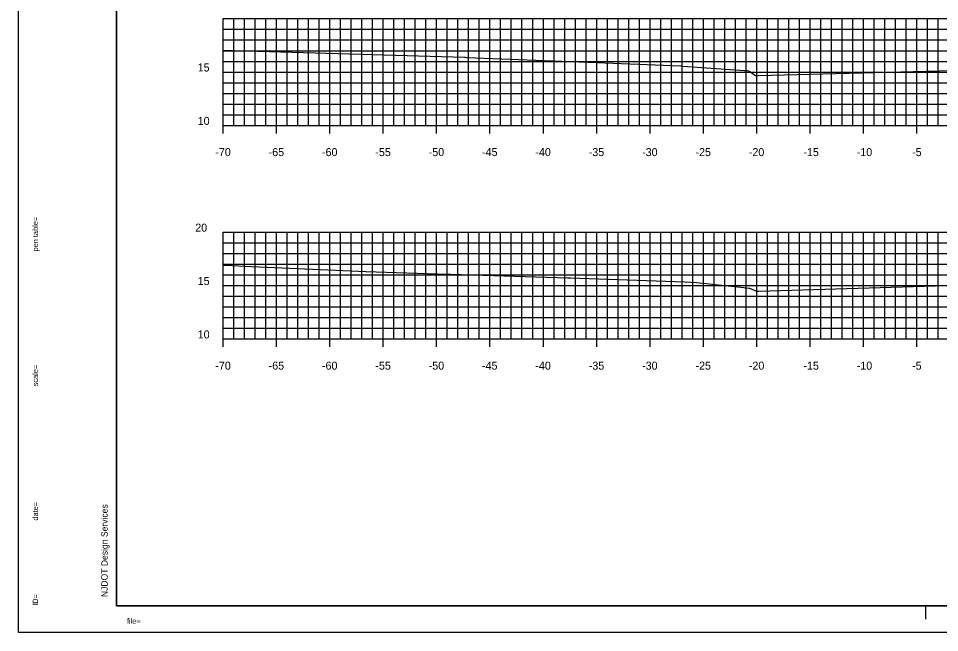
# Model space of a CAD drawing. Extents: x 40011 to 50684, y 49949 to 72236.
# Drawn here: x 40293.9 to 40380.3, y 71574.2 to 71631.7 of the extents above; entities that cross this region are included whole.
import ezdxf

# ---------------------------------------------------------------- set-up
doc = ezdxf.new("R2010")
doc.units = 0
for name, color, linetype in [('1', 7, 'Continuous'), ('41', 7, 'Continuous'), ('51', 7, 'Continuous'), ('52', 7, 'Continuous'), ('53', 7, 'Continuous'), ('54', 7, 'Continuous'), ('55', 7, 'Continuous'), ('57', 7, 'Continuous')]:
    doc.layers.add(name, color=color, linetype=linetype)

msp = doc.modelspace()

# ---------------------------------------------------------------- linework, layer by layer
at = {"layer": '1'}
for p, q in [((40303.141, 71681.691), (40303.141, 71576.691)), ((40303.141, 71576.691), (40468.141, 71576.691)), ((40378.974, 71575.441), (40378.974, 71576.691)), ((40468.641, 71574.191), (40293.946, 71574.191))]:
    msp.add_line(p, q, dxfattribs=at)
at = {"layer": '41'}
for points in [[(40293.946, 71684.191), (40468.641, 71684.191), (40468.641, 71574.191), (40293.946, 71574.191)], [(40303.141, 71681.691), (40468.141, 71681.691), (40468.141, 71576.691), (40303.141, 71576.691)]]:
    msp.add_lwpolyline(points, close=True, dxfattribs=at)
at = {"layer": '51'}
for p, q in [((40313.141, 71621.691), (40313.141, 71631.691)), ((40313.141, 71631.691), (40313.891, 71631.691)), ((40313.141, 71626.691), (40313.891, 71626.691)), ((40313.141, 71621.691), (40313.891, 71621.691)), ((40313.141, 71601.691), (40313.141, 71611.691)), ((40313.141, 71611.691), (40313.891, 71611.691)), ((40313.141, 71606.691), (40313.891, 71606.691)), ((40313.141, 71601.691), (40313.891, 71601.691))]:
    msp.add_line(p, q, dxfattribs=at)
at = {"layer": '52'}
for p, q in [((40313.141, 71621.691), (40453.141, 71621.691)), ((40313.141, 71620.941), (40313.141, 71621.691)), ((40318.141, 71620.941), (40318.141, 71621.691)), ((40323.141, 71620.941), (40323.141, 71621.691)), ((40328.141, 71620.941), (40328.141, 71621.691)), ((40333.141, 71620.941), (40333.141, 71621.691)), ((40338.141, 71620.941), (40338.141, 71621.691)), ((40343.141, 71620.941), (40343.141, 71621.691)), ((40348.141, 71620.941), (40348.141, 71621.691)), ((40353.141, 71620.941), (40353.141, 71621.691)), ((40358.141, 71620.941), (40358.141, 71621.691)), ((40363.141, 71620.941), (40363.141, 71621.691)), ((40368.141, 71620.941), (40368.141, 71621.691)), ((40373.141, 71620.941), (40373.141, 71621.691)), ((40378.141, 71620.941), (40378.141, 71621.691)), ((40313.141, 71601.691), (40453.141, 71601.691)), ((40313.141, 71600.941), (40313.141, 71601.691)), ((40318.141, 71600.941), (40318.141, 71601.691)), ((40323.141, 71600.941), (40323.141, 71601.691)), ((40328.141, 71600.941), (40328.141, 71601.691)), ((40333.141, 71600.941), (40333.141, 71601.691)), ((40338.141, 71600.941), (40338.141, 71601.691)), ((40343.141, 71600.941), (40343.141, 71601.691)), ((40348.141, 71600.941), (40348.141, 71601.691)), ((40353.141, 71600.941), (40353.141, 71601.691)), ((40358.141, 71600.941), (40358.141, 71601.691)), ((40363.141, 71600.941), (40363.141, 71601.691)), ((40368.141, 71600.941), (40368.141, 71601.691)), ((40373.141, 71600.941), (40373.141, 71601.691)), ((40378.141, 71600.941), (40378.141, 71601.691))]:
    msp.add_line(p, q, dxfattribs=at)
at = {"layer": '53'}
for p, q in [((40313.141, 71630.691), (40453.141, 71630.691)), ((40313.141, 71629.691), (40453.141, 71629.691)), ((40313.141, 71628.691), (40453.141, 71628.691)), ((40313.141, 71627.691), (40453.141, 71627.691)), ((40313.141, 71625.691), (40453.141, 71625.691)), ((40313.141, 71624.691), (40453.141, 71624.691)), ((40313.141, 71623.691), (40453.141, 71623.691)), ((40313.141, 71622.691), (40453.141, 71622.691)), ((40313.141, 71610.691), (40453.141, 71610.691)), ((40313.141, 71609.691), (40453.141, 71609.691)), ((40313.141, 71608.691), (40453.141, 71608.691)), ((40313.141, 71607.691), (40453.141, 71607.691)), ((40313.141, 71605.691), (40453.141, 71605.691)), ((40313.141, 71604.691), (40453.141, 71604.691)), ((40313.141, 71603.691), (40453.141, 71603.691)), ((40313.141, 71602.691), (40453.141, 71602.691))]:
    msp.add_line(p, q, dxfattribs=at)
at = {"layer": '54'}
for p, q in [((40314.141, 71621.691), (40314.141, 71631.691)), ((40315.141, 71621.691), (40315.141, 71631.691)), ((40316.141, 71621.691), (40316.141, 71631.691)), ((40317.141, 71621.691), (40317.141, 71631.691)), ((40319.141, 71621.691), (40319.141, 71631.691)), ((40320.141, 71621.691), (40320.141, 71631.691)), ((40321.141, 71621.691), (40321.141, 71631.691)), ((40322.141, 71621.691), (40322.141, 71631.691)), ((40324.141, 71621.691), (40324.141, 71631.691)), ((40325.141, 71621.691), (40325.141, 71631.691)), ((40326.141, 71621.691), (40326.141, 71631.691)), ((40327.141, 71621.691), (40327.141, 71631.691)), ((40329.141, 71621.691), (40329.141, 71631.691)), ((40330.141, 71621.691), (40330.141, 71631.691)), ((40331.141, 71621.691), (40331.141, 71631.691)), ((40332.141, 71621.691), (40332.141, 71631.691)), ((40334.141, 71621.691), (40334.141, 71631.691)), ((40335.141, 71621.691), (40335.141, 71631.691)), ((40336.141, 71621.691), (40336.141, 71631.691)), ((40337.141, 71621.691), (40337.141, 71631.691)), ((40339.141, 71621.691), (40339.141, 71631.691)), ((40340.141, 71621.691), (40340.141, 71631.691)), ((40341.141, 71621.691), (40341.141, 71631.691)), ((40342.141, 71621.691), (40342.141, 71631.691)), ((40344.141, 71621.691), (40344.141, 71631.691)), ((40345.141, 71621.691), (40345.141, 71631.691)), ((40346.141, 71621.691), (40346.141, 71631.691)), ((40347.141, 71621.691), (40347.141, 71631.691)), ((40349.141, 71621.691), (40349.141, 71631.691)), ((40350.141, 71621.691), (40350.141, 71631.691)), ((40351.141, 71621.691), (40351.141, 71631.691)), ((40352.141, 71621.691), (40352.141, 71631.691)), ((40354.141, 71621.691), (40354.141, 71631.691)), ((40355.141, 71621.691), (40355.141, 71631.691)), ((40356.141, 71621.691), (40356.141, 71631.691)), ((40357.141, 71621.691), (40357.141, 71631.691)), ((40359.141, 71621.691), (40359.141, 71631.691)), ((40360.141, 71621.691), (40360.141, 71631.691)), ((40361.141, 71621.691), (40361.141, 71631.691)), ((40362.141, 71621.691), (40362.141, 71631.691)), ((40364.141, 71621.691), (40364.141, 71631.691)), ((40365.141, 71621.691), (40365.141, 71631.691)), ((40366.141, 71621.691), (40366.141, 71631.691)), ((40367.141, 71621.691), (40367.141, 71631.691)), ((40369.141, 71621.691), (40369.141, 71631.691)), ((40370.141, 71621.691), (40370.141, 71631.691)), ((40371.141, 71621.691), (40371.141, 71631.691)), ((40372.141, 71621.691), (40372.141, 71631.691)), ((40374.141, 71621.691), (40374.141, 71631.691)), ((40375.141, 71621.691), (40375.141, 71631.691)), ((40376.141, 71621.691), (40376.141, 71631.691)), ((40377.141, 71621.691), (40377.141, 71631.691)), ((40379.141, 71621.691), (40379.141, 71631.691)), ((40380.141, 71621.691), (40380.141, 71631.691)), ((40314.141, 71601.691), (40314.141, 71611.691)), ((40315.141, 71601.691), (40315.141, 71611.691)), ((40316.141, 71601.691), (40316.141, 71611.691)), ((40317.141, 71601.691), (40317.141, 71611.691)), ((40319.141, 71601.691), (40319.141, 71611.691)), ((40320.141, 71601.691), (40320.141, 71611.691)), ((40321.141, 71601.691), (40321.141, 71611.691)), ((40322.141, 71601.691), (40322.141, 71611.691)), ((40324.141, 71601.691), (40324.141, 71611.691)), ((40325.141, 71601.691), (40325.141, 71611.691)), ((40326.141, 71601.691), (40326.141, 71611.691)), ((40327.141, 71601.691), (40327.141, 71611.691)), ((40329.141, 71601.691), (40329.141, 71611.691)), ((40330.141, 71601.691), (40330.141, 71611.691)), ((40331.141, 71601.691), (40331.141, 71611.691)), ((40332.141, 71601.691), (40332.141, 71611.691)), ((40334.141, 71601.691), (40334.141, 71611.691)), ((40335.141, 71601.691), (40335.141, 71611.691)), ((40336.141, 71601.691), (40336.141, 71611.691)), ((40337.141, 71601.691), (40337.141, 71611.691)), ((40339.141, 71601.691), (40339.141, 71611.691)), ((40340.141, 71601.691), (40340.141, 71611.691)), ((40341.141, 71601.691), (40341.141, 71611.691)), ((40342.141, 71601.691), (40342.141, 71611.691)), ((40344.141, 71601.691), (40344.141, 71611.691)), ((40345.141, 71601.691), (40345.141, 71611.691)), ((40346.141, 71601.691), (40346.141, 71611.691)), ((40347.141, 71601.691), (40347.141, 71611.691)), ((40349.141, 71601.691), (40349.141, 71611.691)), ((40350.141, 71601.691), (40350.141, 71611.691)), ((40351.141, 71601.691), (40351.141, 71611.691)), ((40352.141, 71601.691), (40352.141, 71611.691)), ((40354.141, 71601.691), (40354.141, 71611.691)), ((40355.141, 71601.691), (40355.141, 71611.691)), ((40356.141, 71601.691), (40356.141, 71611.691)), ((40357.141, 71601.691), (40357.141, 71611.691)), ((40359.141, 71601.691), (40359.141, 71611.691)), ((40360.141, 71601.691), (40360.141, 71611.691)), ((40361.141, 71601.691), (40361.141, 71611.691)), ((40362.141, 71601.691), (40362.141, 71611.691)), ((40364.141, 71601.691), (40364.141, 71611.691)), ((40365.141, 71601.691), (40365.141, 71611.691)), ((40366.141, 71601.691), (40366.141, 71611.691)), ((40367.141, 71601.691), (40367.141, 71611.691)), ((40369.141, 71601.691), (40369.141, 71611.691)), ((40370.141, 71601.691), (40370.141, 71611.691)), ((40371.141, 71601.691), (40371.141, 71611.691)), ((40372.141, 71601.691), (40372.141, 71611.691)), ((40374.141, 71601.691), (40374.141, 71611.691)), ((40375.141, 71601.691), (40375.141, 71611.691)), ((40376.141, 71601.691), (40376.141, 71611.691)), ((40377.141, 71601.691), (40377.141, 71611.691)), ((40379.141, 71601.691), (40379.141, 71611.691)), ((40380.141, 71601.691), (40380.141, 71611.691))]:
    msp.add_line(p, q, dxfattribs=at)
at = {"layer": '55'}
for p, q in [((40313.141, 71631.691), (40453.141, 71631.691)), ((40313.141, 71621.691), (40313.141, 71631.691)), ((40318.141, 71621.691), (40318.141, 71631.691)), ((40323.141, 71621.691), (40323.141, 71631.691)), ((40328.141, 71621.691), (40328.141, 71631.691)), ((40333.141, 71621.691), (40333.141, 71631.691)), ((40338.141, 71621.691), (40338.141, 71631.691)), ((40343.141, 71621.691), (40343.141, 71631.691)), ((40348.141, 71621.691), (40348.141, 71631.691)), ((40353.141, 71621.691), (40353.141, 71631.691)), ((40358.141, 71621.691), (40358.141, 71631.691)), ((40363.141, 71621.691), (40363.141, 71631.691)), ((40368.141, 71621.691), (40368.141, 71631.691)), ((40373.141, 71621.691), (40373.141, 71631.691)), ((40378.141, 71621.691), (40378.141, 71631.691)), ((40313.141, 71626.691), (40453.141, 71626.691)), ((40313.141, 71621.691), (40453.141, 71621.691)), ((40313.141, 71611.691), (40453.141, 71611.691)), ((40313.141, 71601.691), (40313.141, 71611.691)), ((40318.141, 71601.691), (40318.141, 71611.691)), ((40323.141, 71601.691), (40323.141, 71611.691)), ((40328.141, 71601.691), (40328.141, 71611.691)), ((40333.141, 71601.691), (40333.141, 71611.691)), ((40338.141, 71601.691), (40338.141, 71611.691)), ((40343.141, 71601.691), (40343.141, 71611.691)), ((40348.141, 71601.691), (40348.141, 71611.691)), ((40353.141, 71601.691), (40353.141, 71611.691)), ((40358.141, 71601.691), (40358.141, 71611.691)), ((40363.141, 71601.691), (40363.141, 71611.691)), ((40368.141, 71601.691), (40368.141, 71611.691)), ((40373.141, 71601.691), (40373.141, 71611.691)), ((40378.141, 71601.691), (40378.141, 71611.691)), ((40313.141, 71606.691), (40453.141, 71606.691)), ((40313.141, 71601.691), (40453.141, 71601.691))]:
    msp.add_line(p, q, dxfattribs=at)
at = {"layer": '57'}
for points in [[(40313.141, 71628.752), (40335.741, 71628.075), (40335.811, 71628.072), (40335.97, 71628.065), (40347.301, 71627.614), (40355.981, 71627.258), (40356.225, 71627.251), (40361.992, 71626.831), (40362.259, 71626.822), (40362.381, 71626.808), (40362.389, 71626.809), (40363.04, 71626.378), (40363.067, 71626.36), (40363.27, 71626.369), (40381.502, 71626.84)], [(40313.141, 71608.606), (40313.373, 71608.593), (40315.8, 71608.474), (40326.508, 71607.997), (40334.177, 71607.759), (40334.463, 71607.749), (40345.427, 71607.43), (40345.435, 71607.43), (40345.643, 71607.422), (40356.411, 71607.032), (40357.483, 71606.973), (40361.922, 71606.496), (40362.057, 71606.48), (40362.446, 71606.452), (40362.453, 71606.448), (40363.111, 71606.165), (40363.33, 71606.171), (40382.941, 71606.763)]]:
    msp.add_lwpolyline(points, dxfattribs=at)

# ---------------------------------------------------------------- texts
at = {"layer": '1'}
for s, height, rotation, p in [('...................pentable..................', 0.0072, 90, (40295.779, 71613.869)), ('pen table=', 0.5, 90, (40295.779, 71609.885)), ('......scale......', 0.0072, 90, (40295.779, 71599.703)), ('scale=', 0.5, 90, (40295.779, 71597.257)), ('.......time......', 0.0072, 90, (40295.779, 71586.869)), ('date=', 0.5, 90, (40295.779, 71584.681)), ('NJDOT Design Services', 0.6, 90, (40302.308, 71577.513)), ('............who............', 0.0072, 90, (40295.779, 71578.024)), ('ID=', 0.5, 90, (40295.779, 71576.696)), ('file=', 0.5, 360, (40304.114, 71575.024)), ('...................bob..................', 0.0072, 360, (40305.779, 71575.024))]:
    msp.add_text(s, height=height, rotation=rotation, dxfattribs=at).set_placement(p)
at = {"layer": '51'}
for s, height, p in [('15', 0.75, (40310.748, 71626.741)), ('10', 0.75, (40310.748, 71621.741)), ('-', 0.0001, (40313.141, 71621.691)), ('20', 0.75, (40310.52, 71611.741)), ('15', 0.75, (40310.748, 71606.741)), ('10', 0.75, (40310.748, 71601.741)), ('-', 0.0001, (40313.141, 71601.691))]:
    msp.add_text(s, height=height, dxfattribs=at).set_placement(p)
at = {"layer": '52'}
for s, p in [('-70', (40312.401, 71618.816)), ('-65', (40317.396, 71618.816)), ('-60', (40322.396, 71618.816)), ('-55', (40327.398, 71618.816)), ('-50', (40332.398, 71618.816)), ('-45', (40337.393, 71618.816)), ('-40', (40342.393, 71618.816)), ('-35', (40347.397, 71618.816)), ('-30', (40352.397, 71618.816)), ('-25', (40357.401, 71618.816)), ('-20', (40362.401, 71618.816)), ('-15', (40367.515, 71618.816)), ('-10', (40372.515, 71618.816)), ('-5', (40377.7, 71618.816)), ('-70', (40312.401, 71598.816)), ('-65', (40317.396, 71598.816)), ('-60', (40322.396, 71598.816)), ('-55', (40327.398, 71598.816)), ('-50', (40332.398, 71598.816)), ('-45', (40337.393, 71598.816)), ('-40', (40342.393, 71598.816)), ('-35', (40347.397, 71598.816)), ('-30', (40352.397, 71598.816)), ('-25', (40357.401, 71598.816)), ('-20', (40362.401, 71598.816)), ('-15', (40367.515, 71598.816)), ('-10', (40372.515, 71598.816)), ('-5', (40377.7, 71598.816))]:
    msp.add_text(s, height=0.75, dxfattribs=at).set_placement(p)

doc.saveas('drawing.dxf')
